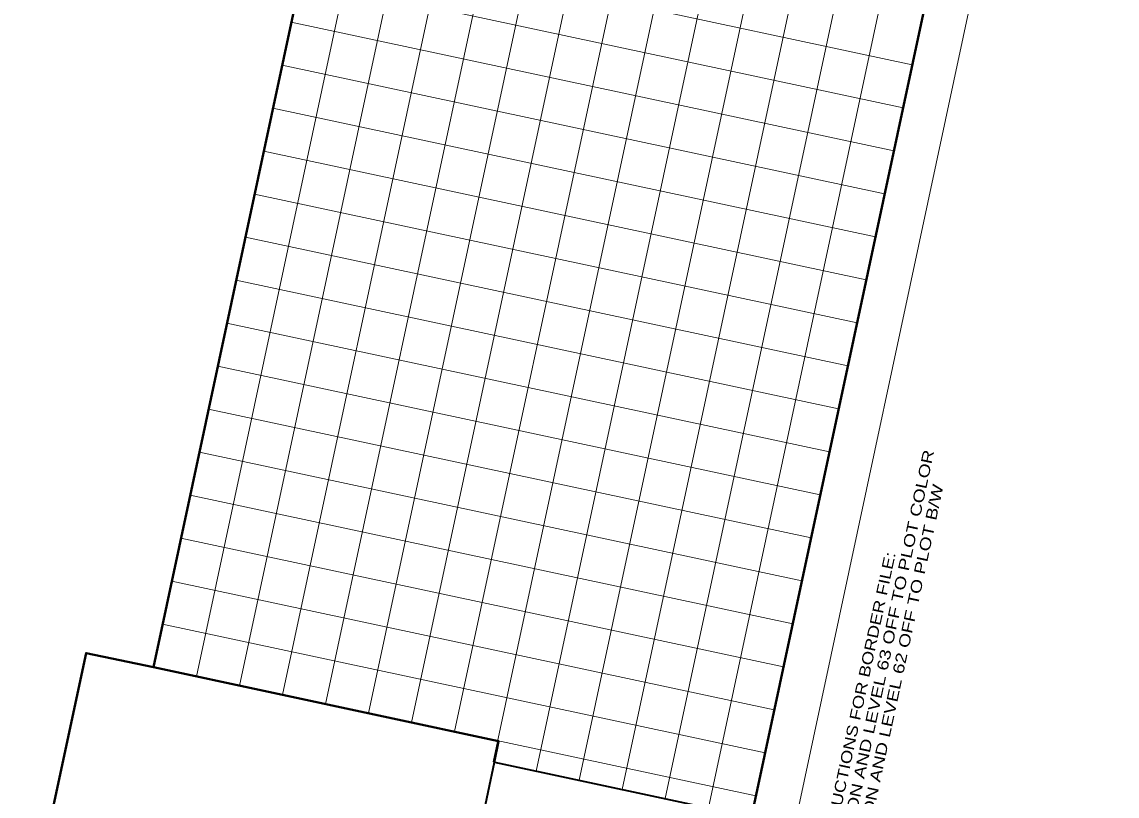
# Model space of a CAD drawing. Extents: x 2363411 to 2369126, y 6976878 to 6988319.
# Drawn here: x 2365334 to 2367822, y 6978000 to 6979761 of the extents above; entities that cross this region are included whole.
import ezdxf

# ---------------------------------------------------------------- set-up
doc = ezdxf.new("R2010")
doc.units = 0
doc.header["$LTSCALE"] = 2
for name, color, linetype, lineweight in [('40', 7, 'Continuous', 13), ('62', 7, 'Continuous', 13), ('63', 7, 'Continuous', 13)]:
    doc.layers.add(name, color=color, linetype=linetype, lineweight=lineweight)

msp = doc.modelspace()

# ---------------------------------------------------------------- linework, layer by layer
at = {"layer": '40', "lineweight": 40}
msp.add_line((2367492.078, 6986997.24), (2365632.322, 6978293.305), dxfattribs=at)
at = {"layer": '40'}
for p, q in [((2367589.875, 6986976.344), (2365730.119, 6978272.409)), ((2367687.672, 6986955.447), (2365827.917, 6978251.513)), ((2367785.47, 6986934.551), (2365925.712, 6978230.617)), ((2367883.266, 6986913.655), (2366023.51, 6978209.72)), ((2368078.861, 6986871.862), (2366219.104, 6978167.928)), ((2368284.696, 6986878), (2366404.457, 6978078.207)), ((2368176.658, 6986850.965), (2366316.901, 6978147.032)), ((2368382.492, 6986857.104), (2366502.254, 6978057.311)), ((2368480.289, 6986836.208), (2366600.051, 6978036.415)), ((2368578.086, 6986815.312), (2366697.848, 6978015.519)), ((2368675.884, 6986794.415), (2366795.645, 6977994.623)), ((2368773.68, 6986773.519), (2366893.442, 6977973.727)), ((2367770.644, 6985907.964), (2366121.307, 6978188.824)), ((2365987.556, 6979955.855), (2367356.715, 6979663.309)), ((2365966.66, 6979858.057), (2367335.818, 6979565.511)), ((2365945.764, 6979760.26), (2367314.922, 6979467.715)), ((2365924.868, 6979662.463), (2367294.026, 6979369.917)), ((2365903.972, 6979564.666), (2367273.13, 6979272.121)), ((2365883.076, 6979466.869), (2367252.234, 6979174.323)), ((2365862.18, 6979369.072), (2367231.338, 6979076.527)), ((2365841.284, 6979271.275), (2367210.442, 6978978.729)), ((2365820.387, 6979173.477), (2367189.545, 6978880.932)), ((2365799.491, 6979075.681), (2367168.649, 6978783.135)), ((2365778.595, 6978977.884), (2367147.753, 6978685.338)), ((2365757.699, 6978880.087), (2367126.857, 6978587.541)), ((2365736.803, 6978782.29), (2367105.961, 6978489.744)), ((2365715.907, 6978684.493), (2367085.065, 6978391.947)), ((2365695.011, 6978586.696), (2367064.169, 6978294.15)), ((2365674.114, 6978488.899), (2367043.273, 6978196.353)), ((2365653.218, 6978391.102), (2367022.376, 6978098.556)), ((2365632.322, 6978293.305), (2367001.48, 6978000.759))]:
    msp.add_line(p, q, dxfattribs=at)
at = {"layer": '62'}
msp.add_line((2369126.202, 6987466.173), (2366932.108, 6977197.487), dxfattribs=at)
at = {"layer": '62', "lineweight": 40}
for p, q in [((2369007.509, 6987389.272), (2366855.207, 6977316.18)), ((2365632.322, 6978293.305), (2366416.672, 6978125.447)), ((2366416.672, 6978125.447), (2366406.505, 6978076.619))]:
    msp.add_line(p, q, dxfattribs=at)
at = {"layer": '62', "lineweight": 35}
for p, q in [((2366271.525, 6977440.894), (2366407.557, 6978077.545)), ((2366407.557, 6978077.545), (2366991.239, 6977952.831))]:
    msp.add_line(p, q, dxfattribs=at)
at = {"layer": '62', "lineweight": 40}
msp.add_lwpolyline([(2365632.322, 6978293.305), (2365479.329, 6978325.469), (2365333.555, 6977643.225)], dxfattribs=at)
at = {"layer": '63'}
for p, q in [((2369126.202, 6987466.173), (2366932.108, 6977197.487)), ((2367589.876, 6986976.344), (2365730.119, 6978272.409)), ((2367687.673, 6986955.447), (2365827.917, 6978251.513)), ((2367785.47, 6986934.551), (2365925.712, 6978230.617)), ((2367883.267, 6986913.654), (2366023.51, 6978209.72)), ((2368078.862, 6986871.862), (2366219.104, 6978167.928)), ((2368284.696, 6986878), (2366404.457, 6978078.207)), ((2368382.492, 6986857.104), (2366502.254, 6978057.311)), ((2368480.289, 6986836.208), (2366600.051, 6978036.415)), ((2368578.086, 6986815.312), (2366697.848, 6978015.519)), ((2368675.884, 6986794.415), (2366795.645, 6977994.623)), ((2368773.68, 6986773.519), (2366893.442, 6977973.727)), ((2367770.644, 6985907.964), (2366121.307, 6978188.824)), ((2365987.556, 6979955.855), (2367356.715, 6979663.309)), ((2365966.66, 6979858.057), (2367335.818, 6979565.511)), ((2365945.764, 6979760.26), (2367314.922, 6979467.715)), ((2365924.868, 6979662.463), (2367294.026, 6979369.917)), ((2365903.972, 6979564.666), (2367273.13, 6979272.121)), ((2365883.076, 6979466.869), (2367252.234, 6979174.323)), ((2365862.18, 6979369.072), (2367231.338, 6979076.527)), ((2365841.284, 6979271.275), (2367210.442, 6978978.729)), ((2365820.387, 6979173.477), (2367189.545, 6978880.932)), ((2365799.491, 6979075.681), (2367168.649, 6978783.135)), ((2365778.595, 6978977.884), (2367147.753, 6978685.338)), ((2365757.699, 6978880.087), (2367126.857, 6978587.541)), ((2365736.803, 6978782.29), (2367105.961, 6978489.744)), ((2365715.907, 6978684.493), (2367085.065, 6978391.947)), ((2365695.011, 6978586.696), (2367064.169, 6978294.15)), ((2365674.114, 6978488.899), (2367043.273, 6978196.353)), ((2365653.218, 6978391.102), (2367022.376, 6978098.556))]:
    msp.add_line(p, q, dxfattribs=at)
at = {"layer": '63', "lineweight": 40}
msp.add_line((2369007.509, 6987389.272), (2366855.207, 6977316.18), dxfattribs=at)
at = {"layer": '63', "lineweight": 35}
msp.add_line((2366407.557, 6978077.545), (2366991.239, 6977952.831), dxfattribs=at)

# ---------------------------------------------------------------- texts
at = {"layer": '62'}
for s, width, p in [('TURN LEVEL 62 ON AND LEVEL 63 OFF TO PLOT COLOR', 1.3, (2367160.165, 6977629.697)), ('TURN LEVEL 63 ON AND LEVEL 62 OFF TO PLOT B/W', 1.3, (2367196.349, 6977621.963)), ('PLOTTING INSTRUCTIONS FOR BORDER FILE:', 1.25, (2367123.98, 6977637.428))]:
    msp.add_text(s, height=25, rotation=77.939, dxfattribs=dict(at, width=width)).set_placement(p)

doc.saveas('drawing.dxf')
